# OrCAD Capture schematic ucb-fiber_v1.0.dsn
size C; title: UCB_Fiber-Interface; rev: 1.0; company: University of Arkansas (NCREPT); note: 700 W. Research Center Blvd.; note: Fayetteville, AR 72701
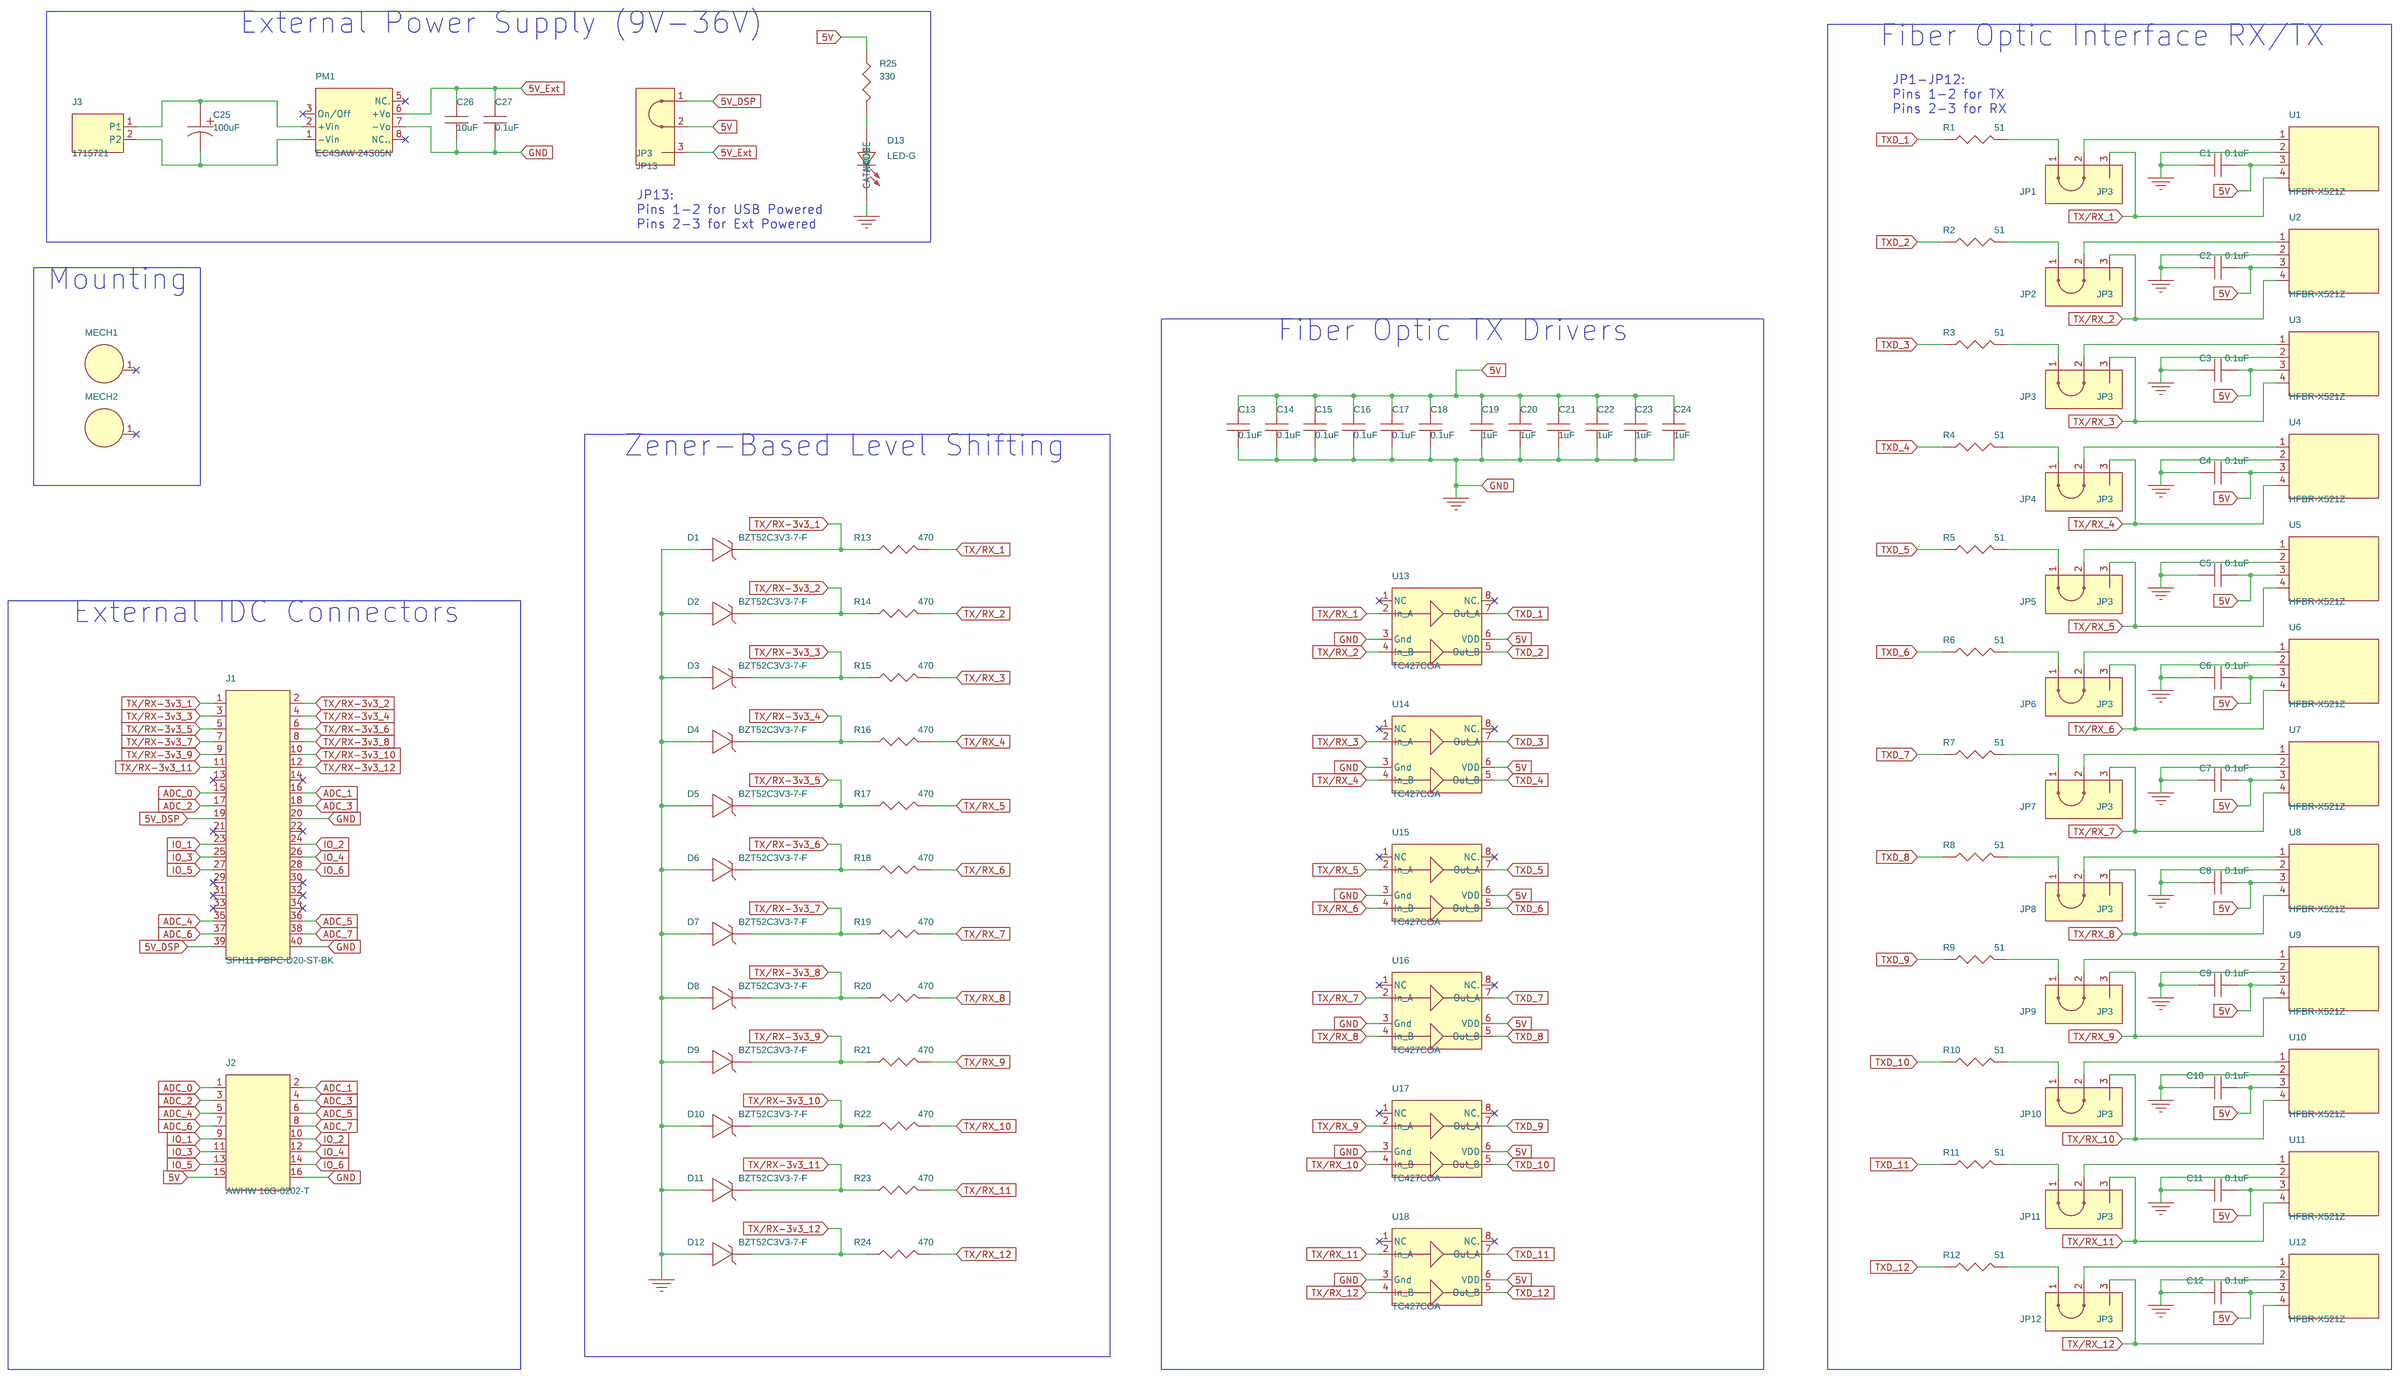
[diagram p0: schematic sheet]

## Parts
C1  0.1uF  [C_0603]
C2  0.1uF  [C_0603]
C3  0.1uF  [C_0603]
C4  0.1uF  [C_0603]
C5  0.1uF  [C_0603]
C6  0.1uF  [C_0603]
C7  0.1uF  [C_0603]
C8  0.1uF  [C_0603]
C9  0.1uF  [C_0603]
C10  0.1uF  [C_0603]
C11  0.1uF  [C_0603]
C12  0.1uF  [C_0603]
C13  0.1uF  [C_0603]
C14  0.1uF  [C_0603]
C15  0.1uF  [C_0603]
C16  0.1uF  [C_0603]
C17  0.1uF  [C_0603]
C18  0.1uF  [C_0603]
C19  1uF  [C_0603]
C20  1uF  [C_0603]
C21  1uF  [C_0603]
C22  1uF  [C_0603]
C23  1uF  [C_0603]
C24  1uF  [C_0603]
C25  100uF  [UVZ1H101MPD]
C26  10uF  [C_1206]
C27  0.1uF  [C_0603]
D1  BZT52C3V3-7-F  [SOD-123]
D2  BZT52C3V3-7-F  [SOD-123]
D3  BZT52C3V3-7-F  [SOD-123]
D4  BZT52C3V3-7-F  [SOD-123]
D5  BZT52C3V3-7-F  [SOD-123]
D6  BZT52C3V3-7-F  [SOD-123]
D7  BZT52C3V3-7-F  [SOD-123]
D8  BZT52C3V3-7-F  [SOD-123]
D9  BZT52C3V3-7-F  [SOD-123]
D10  BZT52C3V3-7-F  [SOD-123]
D11  BZT52C3V3-7-F  [SOD-123]
D12  BZT52C3V3-7-F  [SOD-123]
D13  LED-G  [LED_0805-GREEN]
J1  SFH11-PBPC-D20-ST-BK  [40-IDC-F_MNT]
J2  AWHW 16G-0202-T  [16-IDC-M]
J3  1715721  [1715721]
JP1  JP3  [J_1X3]
JP2  JP3  [J_1X3]
JP3  JP3  [J_1X3]
JP4  JP3  [J_1X3]
JP5  JP3  [J_1X3]
JP6  JP3  [J_1X3]
JP7  JP3  [J_1X3]
JP8  JP3  [J_1X3]
JP9  JP3  [J_1X3]
JP10  JP3  [J_1X3]
JP11  JP3  [J_1X3]
JP12  JP3  [J_1X3]
JP13  JP3  [J_1X3]
MECH1  Mech_Hole  [4-40_SCREW]
MECH2  Mech_Hole  [4-40_SCREW]
PM1  EC4SAW-24S05N  [SIP-8]
R1  51  [R_1206]
R2  51  [R_1206]
R3  51  [R_1206]
R4  51  [R_1206]
R5  51  [R_1206]
R6  51  [R_1206]
R7  51  [R_1206]
R8  51  [R_1206]
R9  51  [R_1206]
R10  51  [R_1206]
R11  51  [R_1206]
R12  51  [R_1206]
R13  470  [R_0805]
R14  470  [R_0805]
R15  470  [R_0805]
R16  470  [R_0805]
R17  470  [R_0805]
R18  470  [R_0805]
R19  470  [R_0805]
R20  470  [R_0805]
R21  470  [R_0805]
R22  470  [R_0805]
R23  470  [R_0805]
R24  470  [R_0805]
R25  330  [R_0805]
U1  HFBR-X521Z  [HFBR-0500Z]
U2  HFBR-X521Z  [HFBR-0500Z]
U3  HFBR-X521Z  [HFBR-0500Z]
U4  HFBR-X521Z  [HFBR-0500Z]
U5  HFBR-X521Z  [HFBR-0500Z]
U6  HFBR-X521Z  [HFBR-0500Z]
U7  HFBR-X521Z  [HFBR-0500Z]
U8  HFBR-X521Z  [HFBR-0500Z]
U9  HFBR-X521Z  [HFBR-0500Z]
U10  HFBR-X521Z  [HFBR-0500Z]
U11  HFBR-X521Z  [HFBR-0500Z]
U12  HFBR-X521Z  [HFBR-0500Z]
U13  TC427COA  [8-SOIC]
U14  TC427COA  [8-SOIC]
U15  TC427COA  [8-SOIC]
U16  TC427COA  [8-SOIC]
U17  TC427COA  [8-SOIC]
U18  TC427COA  [8-SOIC]

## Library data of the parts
C1-C18 C27 = CAP_NP: 0.1µF ±10% 50V X7R MLCC; Manufacturer: TDK; Manufacturer_Part_Number: C1608X7R1H104K080AA; Part_Number: Cap-00001; Tolerance: 10%; Voltage: 50V; Datasheet: TDK-mlcc_commercial_general_en.pdf
C19-C24 = CAP_NP: 1µF ±10% 35V X7R MLCC; Manufacturer: TDK; Manufacturer_Part_Number: C1608X7R1V105K080AC; Part_Number: Cap-00008; Tolerance: 10%; Voltage: 35V; Datasheet: TDK-mlcc_commercial_general_en.pdf
C25 = CAP_P: Electrolytic Capacitor (50V/100uF); Manufacturer: Nichicon; Part_Number: Cap-00020; Voltage: 50V; Datasheet: Nicicon-e-uvz-880014.pdf
C26 = CAP_NP: 10µF ±20% 35V X7R MLCC; Manufacturer: TDK; Manufacturer_Part_Number: C3216X7R1V106M160AC; Part_Number: Cap-00002; Tolerance: 20%; Voltage: 35V; Datasheet: TDK-mlcc_commercial_general_en.pdf
D1-D12 = D-Zener: Zener Diode 3.3V 500mW; Manufacturer: Diodes Incorporated; Part_Number: TMP-216; STEP_Model: SOD-123.step; Datasheet: DiodesInc-ds18004-73542.pdf
D13 = LED: LED, 0805, Green, VF= 2.2V; Manufacturer: OSRAM; Manufacturer_Part_Number: LG R971-KN-1; Part_Number: D-00008; STEP_Model: LED_0805-Green.stp; Datasheet: OSRAM-LGR971-CHIPLED-0805-318376.pdf
J1 = Header_2x20: 40-POS Header, Shrouded, 0.100", TH, Female w/ Mounting; Manufacturer: Sullins; Part_Number: Con-00020; STEP_Model: SFH11-P_ _C-D20-ST-_ _.stp; Datasheet: Sullins-146_PAGE119_.100_SFH11_SERIES_FEMALE_HDR_ST_RA.pdf
J2 = Header_2x8: 16-POS Header, Shrouded, 0.100", TH; Manufacturer: Assmann; Part_Number: Con-00014; STEP_Model: HDB-16.stp; User_Field1: SBH11-PBPC-D08-ST-BK; Datasheet: SBH11-PBPC-D08-ST-BK
J3 = Connector-2: PCB Terminal Block, 2-position, 90 degrees, 5.08mm; Manufacturer: Phoenix Contact; Part_Number: Con-00006; Rating: 17.5A; STEP_Model: 1715721.stp; Voltage: 400V; Datasheet: PhoenixContact-1715734.pdf
JP1-JP13 = JP3: Male, TH, Straight, 3-Pos, 0.1" Pitch; Manufacturer: Various; Manufacturer_Part_Number: PRT-00116; Part_Number: JP-00002
MECH1 MECH2 = Mech_Hole: Mounting Hole for 4-40 Screw, 0.125"; Part_Number: Con-00005
PM1 = EC4SA: Isolated DC/DC Converters 6 Watt, 9-36 Vin, 5 Vout; Manufacturer: Cincon; Part_Number: PS-00002; STEP_Model: PwrMod-SIP8.stp; Datasheet: CINCON-EC4SAW V10-557886.pdf
R1-R12 = R-Standard: 51 Ohm, 1%, 1206; Manufacturer: KOA Speer; Manufacturer_Part_Number: RK73H2BTTD51R0F; Part_Number: TMP-215; Rating: 0.25W; Tolerance: 1%; Datasheet: KOA-RK73H-5715.pdf
R13-R24 = R-Standard: 470 Ohm, 1%, 0805; Manufacturer: KOA Speer; Manufacturer_Part_Number: RK73H2ATTD4700F; Part_Number: Res-00046; Rating: 0.125W; Tolerance: 1%; Datasheet: KOA-RK73H-5715.pdf
R25 = R-Standard: 330 Ohm, 1%, 0805; Manufacturer: KOA Speer; Manufacturer_Part_Number: RK73H2ATTD3300F; Part_Number: Res-00040; Rating: 0.125W; Tolerance: 1%; Datasheet: KOA-RK73H-5715.pdf
U1-U12 = HFBR-X521Z: Fiber Optic, RX/TX, 5MB; Manufacturer: Avago; Part_Number: TMP-209; STEP_Model: HFBR2521.stp; Datasheet: Avago-AV02-1501EN_DS_HFBR-0500Z_2014-09-190.pdf
U13-U18 = TC427COA: MOSFET Driver, 1.5A Dual Non-Inverting; Manufacturer: Microchip; Part_Number: TMP-210; STEP_Model: SOIC08 narrow.stp; Datasheet: Microchip-21415b-1958.pdf

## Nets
5V: C1.2 C2.2 C3.2 C4.2 C5.2 C6.2 C7.2 C8.2 C9.2 C10.2 C11.2 C12.2 C13.1 C14.1 C15.1 C16.1 C17.1 C18.1 C19.1 C20.1 C21.1 C22.1 C23.1 C24.1 J2.15 JP13.2 R25.1 U1.3 U2.3 U3.3 U4.3 U5.3 U6.3 U7.3 U8.3 U9.3 U10.3 U11.3 U12.3 U13.6(VDD) U14.6(VDD) U15.6(VDD) U16.6(VDD) U17.6(VDD) U18.6(VDD)
5V_DSP: J1.19 J1.39 JP13.1
5V_Ext: C26.1 C27.1 JP13.3 PM1.6(+Vo)
GND: C1.1 C2.1 C3.1 C4.1 C5.1 C6.1 C7.1 C8.1 C9.1 C10.1 C11.1 C12.1 C13.2 C14.2 C15.2 C16.2 C17.2 C18.2 C19.2 C20.2 C21.2 C22.2 C23.2 C24.2 C26.2 C27.2 D1.2 D2.2 D3.2 D4.2 D5.2 D6.2 D7.2 D8.2 D9.2 D10.2 D11.2 D12.2 D13.1(CATHODE) J1.20 J1.40 J2.16 PM1.7(-Vo) U1.2 U2.2 U3.2 U4.2 U5.2 U6.2 U7.2 U8.2 U9.2 U10.2 U11.2 U12.2 U13.3(Gnd) U14.3(Gnd) U15.3(Gnd) U16.3(Gnd) U17.3(Gnd) U18.3(Gnd)
ADC_0: J1.15 J2.1
ADC_1: J1.16 J2.2
ADC_2: J1.17 J2.3
ADC_3: J1.18 J2.4
ADC_4: J1.35 J2.5
ADC_5: J1.36 J2.6
ADC_6: J1.37 J2.7
ADC_7: J1.38 J2.8
IO_1: J1.23 J2.9
IO_2: J1.24 J2.10
IO_3: J1.25 J2.11
IO_4: J1.26 J2.12
IO_5: J1.27 J2.13
IO_6: J1.28 J2.14
TX/RX-3v3_1: D1.1 J1.1 R13.1
TX/RX-3v3_2: D2.1 J1.2 R14.1
TX/RX-3v3_3: D3.1 J1.3 R15.1
TX/RX-3v3_4: D4.1 J1.4 R16.1
TX/RX-3v3_5: D5.1 J1.5 R17.1
TX/RX-3v3_6: D6.1 J1.6 R18.1
TX/RX-3v3_7: D7.1 J1.7 R19.1
TX/RX-3v3_8: D8.1 J1.8 R20.1
TX/RX-3v3_9: D9.1 J1.9 R21.1
TX/RX-3v3_10: D10.1 J1.10 R22.1
TX/RX-3v3_11: D11.1 J1.11 R23.1
TX/RX-3v3_12: D12.1 J1.12 R24.1
TX/RX_1: JP1.3 R13.2 U1.4 U13.2(In_A)
TX/RX_2: JP2.3 R14.2 U2.4 U13.4(In_B)
TX/RX_3: JP3.3 R15.2 U3.4 U14.2(In_A)
TX/RX_4: JP4.3 R16.2 U4.4 U14.4(In_B)
TX/RX_5: JP5.3 R17.2 U5.4 U15.2(In_A)
TX/RX_6: JP6.3 R18.2 U6.4 U15.4(In_B)
TX/RX_7: JP7.3 R19.2 U7.4 U16.2(In_A)
TX/RX_8: JP8.3 R20.2 U8.4 U16.4(In_B)
TX/RX_9: JP9.3 R21.2 U9.4 U17.2(In_A)
TX/RX_10: JP10.3 R22.2 U10.4 U17.4(In_B)
TX/RX_11: JP11.3 R23.2 U11.4 U18.2(In_A)
TX/RX_12: JP12.3 R24.2 U12.4 U18.4(In_B)
TXD_1: R1.1 U13.7(Out_A)
TXD_2: R2.1 U13.5(Out_B)
TXD_3: R3.1 U14.7(Out_A)
TXD_4: R4.1 U14.5(Out_B)
TXD_5: R5.1 U15.7(Out_A)
TXD_6: R6.1 U15.5(Out_B)
TXD_7: R7.1 U16.7(Out_A)
TXD_8: R8.1 U16.5(Out_B)
TXD_9: R9.1 U17.7(Out_A)
TXD_10: R10.1 U17.5(Out_B)
TXD_11: R11.1 U18.7(Out_A)
TXD_12: R12.1 U18.5(Out_B)
N01550: JP1.2 U1.1
N02084: JP1.1 R1.2
N02867: JP2.2 U2.1
N02957: JP2.1 R2.2
N03301: JP3.2 U3.1
N03391: JP3.1 R3.2
N03756: JP4.2 U4.1
N03846: JP4.1 R4.2
N04236: JP5.2 U5.1
N04326: JP5.1 R5.2
N05708: JP6.2 U6.1
N05798: JP6.1 R6.2
N05904: JP7.2 U7.1
N05978: JP7.1 R7.2
N06100: JP8.2 U8.1
N06174: JP8.1 R8.2
N06296: JP9.2 U9.1
N06386: JP9.1 R9.2
N06492: JP10.2 U10.1
N06582: JP10.1 R10.2
N07286: JP11.2 U11.1
N07376: JP11.1 R11.2
N07482: JP12.2 U12.1
N07572: JP12.1 R12.2
N25651: C25.1 J3.1(P1) PM1.2(+Vin)
N25663: C25.2 J3.2(P2) PM1.1(-Vin)
N45703: D13.2(ANODE) R25.2

Not connected (* = marked no-connect by the designer): J1 13* 14* 21* 22* 29* 30* 31* 32* 33* 34*; MECH1 1*; MECH2 1*; PM1 3(On/Off)* 5(NC.)* 8(NC..)*; U13 1(NC)* 8(NC.)*; U14 1(NC)* 8(NC.)*; U15 1(NC)* 8(NC.)*; U16 1(NC)* 8(NC.)*; U17 1(NC)* 8(NC.)*; U18 1(NC)* 8(NC.)*

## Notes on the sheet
- External Power Supply (9V-36V)
- Fiber Optic Interface RX/TX
- JP1-JP12:
  Pins 1-2 for TX
  Pins 2-3 for RX
- JP13:
  Pins 1-2 for USB Powered
  Pins 2-3 for Ext Powered
- Mounting
- Fiber Optic TX Drivers
- Zener-Based Level Shifting
- External IDC Connectors
